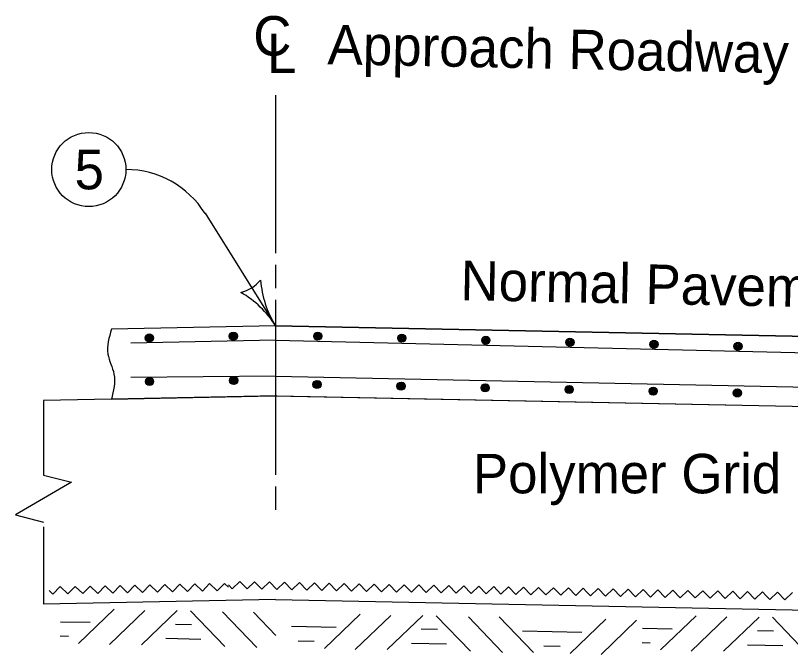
# Model space of a CAD drawing. Extents: x 5546 to 81668, y 3174 to 15999.
# Drawn here: x 17362.5 to 17676.2, y 13836.8 to 14095.5 of the extents above; entities that cross this region are included whole.
import ezdxf

# ---------------------------------------------------------------- set-up
doc = ezdxf.new("R2010")
doc.units = 0
for name, color, linetype in [('PS_BOLT', 7, 'Continuous'), ('PS_CONST', 7, 'Continuous'), ('PS_DIM', 7, 'Continuous'), ('PS_TEXT', 7, 'Continuous')]:
    doc.layers.add(name, color=color, linetype=linetype)

msp = doc.modelspace()

# ---------------------------------------------------------------- linework, layer by layer
at = {"layer": 'PS_BOLT'}
msp.add_line((18199.22, 13934.15), (17467.7, 13949.31), dxfattribs=at)
at = {"layer": 'PS_CONST'}
msp.add_line((17439.18, 14015.41), (17467.75, 13969.86), dxfattribs=at)
for centre, radius, start, end in [((17407.15, 13995.32), 37.81, 32.09, 90), ((17449.85, 13998.4), 15.52, 284.3569, 319.8236), ((17501.78, 13991.2), 40.18, 184.0178, 212.0903), ((17433.71, 13948.52), 40.18, 32.0903, 60.1628)]:
    msp.add_arc(centre, radius, start, end, dxfattribs=at)
at = {"layer": 'PS_DIM'}
for p, q in [((17467.74, 13969.86), (17401.36, 13968.53)), ((17467.74, 13969.86), (17401.36, 13968.53)), ((18178, 13955.6), (17467.74, 13969.86)), ((17467.74, 13969.86), (18178, 13955.6)), ((17467.71, 13964.11), (17409.19, 13962.8)), ((17467.71, 13964.11), (18199.3, 13946.45)), ((17467.71, 13949.54), (17409.18, 13948.92)), ((17468.31, 13941.51), (17401.36, 13940.16)), ((17401.36, 13940.16), (17467.17, 13941.48)), ((17467.17, 13941.51), (17467.74, 13941.5)), ((17467.17, 13941.51), (18216.28, 13926.47)), ((17467.74, 13941.5), (17468.31, 13941.51)), ((17468.31, 13941.48), (18216.28, 13926.47)), ((17401.36, 13940.16), (17373.8, 13939.61)), ((17373.8, 13939.61), (17373.8, 13909.35)), ((17373.8, 13909.35), (17385.15, 13906.52)), ((17385.15, 13906.52), (17373.8, 13899.9)), ((17373.8, 13899.9), (17362.46, 13893.28)), ((17362.46, 13893.28), (17373.8, 13890.44)), ((17373.8, 13888.44), (17373.8, 13857.19)), ((17467.74, 13859.07), (17373.8, 13857.19)), ((17467.74, 13859.07), (18284.33, 13842.68)), ((17402.43, 13855.13), (17388.01, 13841.27)), ((17414.87, 13854.65), (17400.45, 13840.79)), ((17427.88, 13854.61), (17413.46, 13840.76)), ((17433.29, 13854.51), (17447.15, 13840.08)), ((17446.29, 13854.02), (17460.15, 13839.6)), ((17458.75, 13854), (17467.85, 13844.52)), ((17501.96, 13853.13), (17487.54, 13839.27)), ((17514.4, 13852.65), (17499.98, 13838.8)), ((17527.41, 13852.62), (17512.99, 13838.76)), ((17532.82, 13852.51), (17546.68, 13838.09)), ((17545.83, 13852.02), (17559.68, 13837.6)), ((17558.28, 13852), (17572.13, 13837.57)), ((17601.49, 13851.13), (17587.07, 13837.27)), ((17613.94, 13850.65), (17599.51, 13836.8)), ((17638.03, 13852.49), (17623.61, 13838.63)), ((17650.47, 13852.01), (17636.05, 13838.16)), ((17663.48, 13851.98), (17649.06, 13838.12)), ((17668.89, 13851.87), (17682.75, 13837.45))]:
    msp.add_line(p, q, dxfattribs=at)
for points in [[(17467.74, 14063.28), (17467.74, 13999.32)], [(17467.75, 13994.6), (17467.75, 13985.14)], [(17467.74, 13980.41), (17467.74, 13909.51)], [(17418.14, 13964.87), (17417.86, 13965.42), (17417.56, 13966.28), (17416.67, 13966.41), (17415.9, 13966.26), (17415.21, 13965.67), (17415.32, 13964.85), (17415.48, 13963.98), (17416.19, 13963.59), (17416.92, 13963.55), (17417.86, 13964.1), (17417.91, 13964.74), (17417.66, 13965.6), (17417.07, 13966.29), (17416.25, 13966.23), (17415.61, 13965.65), (17415.57, 13964.87), (17415.77, 13964), (17416.27, 13963.89), (17416.86, 13963.74), (17417.56, 13964.18), (17417.52, 13964.81), (17417.37, 13965.53), (17416.94, 13966.04), (17416.23, 13965.74), (17415.83, 13965.18), (17415.84, 13964.44), (17416.24, 13964.28), (17416.69, 13964.07), (17417.25, 13964.45), (17417.36, 13965), (17417.08, 13965.46), (17416.54, 13965.47), (17416.17, 13965.2), (17416.06, 13964.71), (17416.28, 13964.48), (17416.58, 13964.35), (17416.99, 13964.62), (17417.07, 13964.98), (17416.85, 13965.3), (17416.56, 13965.23), (17416.38, 13964.97), (17416.41, 13964.63), (17416.65, 13964.65), (17416.77, 13964.95)], [(17452.17, 13965.63), (17451.9, 13966.18), (17451.59, 13967.04), (17450.7, 13967.16), (17449.94, 13967.01), (17449.24, 13966.43), (17449.35, 13965.6), (17449.51, 13964.74), (17450.22, 13964.35), (17450.95, 13964.3), (17451.89, 13964.86), (17451.94, 13965.5), (17451.69, 13966.36), (17451.1, 13967.05), (17450.28, 13966.99), (17449.64, 13966.41), (17449.6, 13965.62), (17449.8, 13964.76), (17450.3, 13964.65), (17450.89, 13964.5), (17451.59, 13964.94), (17451.55, 13965.57), (17451.4, 13966.29), (17450.98, 13966.79), (17450.26, 13966.5), (17449.86, 13965.94), (17449.87, 13965.2), (17450.27, 13965.04), (17450.72, 13964.82), (17451.28, 13965.21), (17451.39, 13965.75), (17451.11, 13966.22), (17450.57, 13966.23), (17450.2, 13965.96), (17450.09, 13965.46), (17450.31, 13965.23), (17450.61, 13965.11), (17451.03, 13965.38), (17451.1, 13965.73), (17450.88, 13966.06), (17450.59, 13965.99), (17450.42, 13965.73), (17450.44, 13965.39), (17450.68, 13965.41), (17450.81, 13965.71)], [(17483.32, 13965.6), (17483.59, 13966.15), (17483.9, 13967), (17484.79, 13967.13), (17485.56, 13966.98), (17486.24, 13966.39), (17486.14, 13965.57), (17485.97, 13964.7), (17485.26, 13964.32), (17484.53, 13964.27), (17483.59, 13964.83), (17483.54, 13965.46), (17483.8, 13966.33), (17484.39, 13967.01), (17485.21, 13966.95), (17485.85, 13966.37), (17485.89, 13965.59), (17485.68, 13964.73), (17485.19, 13964.61), (17484.59, 13964.46), (17483.89, 13964.9), (17483.94, 13965.54), (17484.09, 13966.25), (17484.52, 13966.76), (17485.23, 13966.47), (17485.62, 13965.9), (17485.62, 13965.17), (17485.22, 13965), (17484.76, 13964.79), (17484.21, 13965.17), (17484.1, 13965.72), (17484.38, 13966.19), (17484.92, 13966.2), (17485.28, 13965.93), (17485.39, 13965.43), (17485.18, 13965.2), (17484.88, 13965.08), (17484.46, 13965.35), (17484.39, 13965.7), (17484.61, 13966.02), (17484.9, 13965.95), (17485.07, 13965.7), (17485.05, 13965.36), (17484.81, 13965.37), (17484.68, 13965.68)], [(17517.35, 13964.78), (17517.62, 13965.33), (17517.93, 13966.18), (17518.82, 13966.31), (17519.59, 13966.16), (17520.28, 13965.57), (17520.17, 13964.75), (17520, 13963.88), (17519.3, 13963.49), (17518.56, 13963.45), (17517.62, 13964.01), (17517.57, 13964.65), (17517.83, 13965.5), (17518.42, 13966.19), (17519.24, 13966.13), (17519.88, 13965.55), (17519.92, 13964.77), (17519.71, 13963.9), (17519.22, 13963.79), (17518.62, 13963.64), (17517.92, 13964.08), (17517.97, 13964.71), (17518.12, 13965.43), (17518.55, 13965.94), (17519.26, 13965.64), (17519.65, 13965.08), (17519.65, 13964.35), (17519.25, 13964.18), (17518.79, 13963.97), (17518.24, 13964.35), (17518.13, 13964.9), (17518.41, 13965.37), (17518.94, 13965.38), (17519.31, 13965.1), (17519.42, 13964.61), (17519.21, 13964.38), (17518.91, 13964.25), (17518.49, 13964.53), (17518.42, 13964.88), (17518.64, 13965.2), (17518.93, 13965.13), (17519.11, 13964.88), (17519.07, 13964.54), (17518.84, 13964.55), (17518.71, 13964.86)], [(17551.38, 13963.96), (17551.65, 13964.5), (17551.96, 13965.36), (17552.85, 13965.49), (17553.62, 13965.33), (17554.3, 13964.75), (17554.19, 13963.92), (17554.03, 13963.06), (17553.32, 13962.67), (17552.59, 13962.63), (17551.65, 13963.19), (17551.6, 13963.82), (17551.86, 13964.69), (17552.44, 13965.37), (17553.27, 13965.31), (17553.91, 13964.73), (17553.95, 13963.94), (17553.74, 13963.08), (17553.25, 13962.97), (17552.65, 13962.82), (17551.95, 13963.26), (17552, 13963.89), (17552.15, 13964.61), (17552.58, 13965.12), (17553.29, 13964.82), (17553.68, 13964.25), (17553.68, 13963.53), (17553.28, 13963.36), (17552.82, 13963.15), (17552.27, 13963.53), (17552.15, 13964.07), (17552.44, 13964.54), (17552.97, 13964.56), (17553.34, 13964.28), (17553.45, 13963.79), (17553.24, 13963.56), (17552.94, 13963.43), (17552.52, 13963.71), (17552.45, 13964.05), (17552.67, 13964.38), (17552.96, 13964.31), (17553.13, 13964.06), (17553.1, 13963.71), (17552.87, 13963.73), (17552.74, 13964.03)], [(17585.41, 13963.13), (17585.68, 13963.68), (17585.99, 13964.54), (17586.88, 13964.67), (17587.65, 13964.51), (17588.33, 13963.93), (17588.22, 13963.1), (17588.06, 13962.24), (17587.35, 13961.85), (17586.62, 13961.81), (17585.68, 13962.36), (17585.63, 13963), (17585.89, 13963.86), (17586.48, 13964.55), (17587.3, 13964.49), (17587.94, 13963.9), (17587.98, 13963.12), (17587.77, 13962.26), (17587.28, 13962.15), (17586.68, 13962), (17585.98, 13962.44), (17586.03, 13963.07), (17586.18, 13963.79), (17586.61, 13964.3), (17587.32, 13964), (17587.71, 13963.44), (17587.71, 13962.7), (17587.31, 13962.54), (17586.85, 13962.33), (17586.3, 13962.71), (17586.19, 13963.26), (17586.47, 13963.72), (17587, 13963.73), (17587.37, 13963.46), (17587.48, 13962.96), (17587.27, 13962.74), (17586.97, 13962.61), (17586.55, 13962.89), (17586.48, 13963.23), (17586.7, 13963.56), (17586.98, 13963.49), (17587.16, 13963.23), (17587.13, 13962.89), (17586.9, 13962.91), (17586.77, 13963.21)], [(17619.43, 13962.31), (17619.71, 13962.86), (17620.02, 13963.72), (17620.91, 13963.84), (17621.68, 13963.69), (17622.36, 13963.11), (17622.26, 13962.28), (17622.09, 13961.42), (17621.38, 13961.03), (17620.65, 13960.99), (17619.71, 13961.54), (17619.66, 13962.18), (17619.92, 13963.04), (17620.51, 13963.73), (17621.33, 13963.67), (17621.97, 13963.08), (17622.01, 13962.3), (17621.8, 13961.44), (17621.31, 13961.33), (17620.71, 13961.18), (17620.01, 13961.62), (17620.06, 13962.25), (17620.21, 13962.97), (17620.63, 13963.48), (17621.35, 13963.18), (17621.74, 13962.61), (17621.74, 13961.88), (17621.33, 13961.72), (17620.88, 13961.51), (17620.33, 13961.89), (17620.21, 13962.43), (17620.5, 13962.9), (17621.03, 13962.91), (17621.4, 13962.64), (17621.51, 13962.14), (17621.3, 13961.91), (17621, 13961.79), (17620.58, 13962.07), (17620.51, 13962.41), (17620.73, 13962.74), (17621.01, 13962.67), (17621.19, 13962.41), (17621.16, 13962.07), (17620.92, 13962.09), (17620.8, 13962.39)], [(17653.47, 13961.49), (17653.74, 13962.04), (17654.05, 13962.9), (17654.94, 13963.03), (17655.71, 13962.87), (17656.39, 13962.28), (17656.29, 13961.46), (17656.12, 13960.6), (17655.41, 13960.21), (17654.68, 13960.17), (17653.74, 13960.72), (17653.69, 13961.36), (17653.95, 13962.22), (17654.54, 13962.91), (17655.36, 13962.85), (17656, 13962.26), (17656.04, 13961.48), (17655.83, 13960.62), (17655.34, 13960.51), (17654.74, 13960.36), (17654.04, 13960.8), (17654.09, 13961.43), (17654.24, 13962.15), (17654.66, 13962.66), (17655.38, 13962.36), (17655.77, 13961.8), (17655.77, 13961.06), (17655.36, 13960.9), (17654.91, 13960.68), (17654.35, 13961.07), (17654.25, 13961.62), (17654.53, 13962.08), (17655.06, 13962.09), (17655.43, 13961.82), (17655.54, 13961.32), (17655.33, 13961.1), (17655.03, 13960.97), (17654.61, 13961.24), (17654.54, 13961.59), (17654.76, 13961.91), (17655.05, 13961.85), (17655.22, 13961.59), (17655.19, 13961.25), (17654.95, 13961.27), (17654.83, 13961.57)], [(17418.26, 13947.26), (17418, 13947.81), (17417.7, 13948.67), (17416.81, 13948.81), (17416.04, 13948.67), (17415.35, 13948.09), (17415.45, 13947.27), (17415.59, 13946.4), (17416.3, 13946), (17417.04, 13945.95), (17417.98, 13946.5), (17418.04, 13947.13), (17417.79, 13948), (17417.21, 13948.69), (17416.39, 13948.64), (17415.74, 13948.07), (17415.69, 13947.28), (17415.89, 13946.42), (17416.38, 13946.3), (17416.98, 13946.14), (17417.68, 13946.57), (17417.64, 13947.21), (17417.5, 13947.93), (17417.08, 13948.44), (17416.37, 13948.15), (17415.96, 13947.59), (17415.96, 13946.86), (17416.36, 13946.69), (17416.81, 13946.48), (17417.37, 13946.85), (17417.48, 13947.39), (17417.22, 13947.86), (17416.68, 13947.88), (17416.3, 13947.61), (17416.18, 13947.12), (17416.39, 13946.89), (17416.69, 13946.76), (17417.11, 13947.03), (17417.19, 13947.38), (17416.98, 13947.7), (17416.69, 13947.63), (17416.51, 13947.38), (17416.53, 13947.04), (17416.77, 13947.06), (17416.9, 13947.36)], [(17452.3, 13947.63), (17452.03, 13948.18), (17451.74, 13949.04), (17450.85, 13949.18), (17450.08, 13949.04), (17449.39, 13948.45), (17449.48, 13947.63), (17449.63, 13946.77), (17450.34, 13946.37), (17451.07, 13946.31), (17452.01, 13946.86), (17452.08, 13947.49), (17451.83, 13948.36), (17451.25, 13949.05), (17450.43, 13949.01), (17449.78, 13948.43), (17449.73, 13947.65), (17449.93, 13946.78), (17450.42, 13946.67), (17451.01, 13946.5), (17451.72, 13946.94), (17451.68, 13947.57), (17451.54, 13948.29), (17451.12, 13948.8), (17450.4, 13948.52), (17450, 13947.96), (17449.99, 13947.23), (17450.4, 13947.05), (17450.84, 13946.84), (17451.41, 13947.21), (17451.52, 13947.76), (17451.25, 13948.23), (17450.71, 13948.25), (17450.34, 13947.98), (17450.22, 13947.48), (17450.43, 13947.25), (17450.73, 13947.12), (17451.15, 13947.39), (17451.23, 13947.74), (17451.02, 13948.07), (17450.73, 13948), (17450.55, 13947.74), (17450.57, 13947.41), (17450.81, 13947.42), (17450.94, 13947.72)], [(17486.03, 13946), (17485.78, 13946.55), (17485.51, 13947.42), (17484.63, 13947.59), (17483.86, 13947.47), (17483.14, 13946.92), (17483.22, 13946.09), (17483.34, 13945.22), (17484.03, 13944.8), (17484.76, 13944.72), (17485.72, 13945.23), (17485.8, 13945.87), (17485.58, 13946.74), (17485.03, 13947.45), (17484.2, 13947.43), (17483.53, 13946.88), (17483.46, 13946.09), (17483.63, 13945.23), (17484.12, 13945.09), (17484.71, 13944.91), (17485.43, 13945.32), (17485.41, 13945.96), (17485.29, 13946.68), (17484.89, 13947.21), (17484.17, 13946.95), (17483.74, 13946.4), (17483.72, 13945.66), (17484.11, 13945.48), (17484.56, 13945.25), (17485.13, 13945.61), (17485.26, 13946.15), (17485, 13946.63), (17484.47, 13946.66), (17484.09, 13946.41), (17483.95, 13945.91), (17484.15, 13945.68), (17484.45, 13945.54), (17484.88, 13945.8), (17484.97, 13946.14), (17484.76, 13946.48), (17484.47, 13946.42), (17484.29, 13946.17), (17484.29, 13945.83), (17484.54, 13945.83), (17484.67, 13946.13)], [(17520.07, 13945.31), (17519.81, 13945.87), (17519.54, 13946.74), (17518.67, 13946.91), (17517.89, 13946.79), (17517.18, 13946.23), (17517.25, 13945.41), (17517.37, 13944.53), (17518.07, 13944.11), (17518.8, 13944.04), (17519.75, 13944.56), (17519.84, 13945.19), (17519.62, 13946.06), (17519.06, 13946.77), (17518.23, 13946.75), (17517.56, 13946.19), (17517.49, 13945.41), (17517.66, 13944.54), (17518.15, 13944.41), (17518.75, 13944.23), (17519.46, 13944.64), (17519.44, 13945.27), (17519.32, 13946), (17518.92, 13946.53), (17518.2, 13946.26), (17517.77, 13945.71), (17517.75, 13944.98), (17518.14, 13944.8), (17518.59, 13944.57), (17519.16, 13944.93), (17519.29, 13945.47), (17519.04, 13945.94), (17518.5, 13945.98), (17518.12, 13945.72), (17517.98, 13945.23), (17518.18, 13945), (17518.48, 13944.85), (17518.91, 13945.12), (17519, 13945.46), (17518.8, 13945.79), (17518.51, 13945.74), (17518.32, 13945.49), (17518.33, 13945.14), (17518.57, 13945.15), (17518.71, 13945.45)], [(17554.1, 13944.63), (17553.85, 13945.19), (17553.58, 13946.06), (17552.69, 13946.22), (17551.93, 13946.1), (17551.21, 13945.55), (17551.28, 13944.72), (17551.4, 13943.85), (17552.1, 13943.44), (17552.83, 13943.36), (17553.79, 13943.87), (17553.87, 13944.5), (17553.65, 13945.38), (17553.09, 13946.09), (17552.27, 13946.06), (17551.6, 13945.51), (17551.53, 13944.73), (17551.69, 13943.86), (17552.19, 13943.73), (17552.78, 13943.55), (17553.49, 13943.96), (17553.47, 13944.59), (17553.36, 13945.32), (17552.95, 13945.84), (17552.23, 13945.58), (17551.81, 13945.03), (17551.78, 13944.3), (17552.17, 13944.11), (17552.62, 13943.88), (17553.2, 13944.24), (17553.32, 13944.78), (17553.07, 13945.26), (17552.53, 13945.29), (17552.15, 13945.04), (17552.02, 13944.55), (17552.22, 13944.31), (17552.52, 13944.17), (17552.94, 13944.43), (17553.03, 13944.77), (17552.83, 13945.11), (17552.54, 13945.05), (17552.35, 13944.8), (17552.36, 13944.46), (17552.61, 13944.47), (17552.74, 13944.76)], [(17588.13, 13943.94), (17587.88, 13944.5), (17587.61, 13945.37), (17586.73, 13945.54), (17585.96, 13945.42), (17585.24, 13944.86), (17585.32, 13944.04), (17585.44, 13943.17), (17586.13, 13942.75), (17586.86, 13942.67), (17587.82, 13943.19), (17587.9, 13943.82), (17587.68, 13944.69), (17587.12, 13945.41), (17586.3, 13945.38), (17585.63, 13944.82), (17585.56, 13944.05), (17585.73, 13943.17), (17586.22, 13943.04), (17586.81, 13942.87), (17587.53, 13943.28), (17587.51, 13943.91), (17587.39, 13944.63), (17586.99, 13945.16), (17586.27, 13944.89), (17585.84, 13944.35), (17585.82, 13943.61), (17586.21, 13943.44), (17586.65, 13943.2), (17587.23, 13943.56), (17587.35, 13944.1), (17587.1, 13944.58), (17586.56, 13944.61), (17586.18, 13944.36), (17586.05, 13943.86), (17586.25, 13943.63), (17586.55, 13943.49), (17586.98, 13943.75), (17587.06, 13944.09), (17586.86, 13944.42), (17586.57, 13944.37), (17586.38, 13944.12), (17586.39, 13943.78), (17586.64, 13943.79), (17586.77, 13944.08)], [(17622.16, 13943.26), (17621.91, 13943.82), (17621.65, 13944.69), (17620.76, 13944.86), (17619.99, 13944.74), (17619.27, 13944.18), (17619.35, 13943.36), (17619.47, 13942.49), (17620.16, 13942.07), (17620.9, 13941.99), (17621.85, 13942.5), (17621.93, 13943.14), (17621.71, 13944.01), (17621.16, 13944.72), (17620.33, 13944.7), (17619.67, 13944.14), (17619.59, 13943.36), (17619.76, 13942.49), (17620.25, 13942.36), (17620.84, 13942.18), (17621.56, 13942.59), (17621.54, 13943.23), (17621.43, 13943.95), (17621.02, 13944.47), (17620.3, 13944.21), (17619.87, 13943.67), (17619.85, 13942.93), (17620.24, 13942.75), (17620.69, 13942.52), (17621.26, 13942.87), (17621.39, 13943.42), (17621.13, 13943.9), (17620.6, 13943.93), (17620.21, 13943.67), (17620.08, 13943.18), (17620.28, 13942.95), (17620.58, 13942.81), (17621.01, 13943.06), (17621.1, 13943.4), (17620.9, 13943.74), (17620.6, 13943.69), (17620.42, 13943.44), (17620.42, 13943.09), (17620.67, 13943.1), (17620.81, 13943.4)], [(17656.2, 13942.58), (17655.95, 13943.14), (17655.68, 13944), (17654.8, 13944.17), (17654.02, 13944.06), (17653.31, 13943.5), (17653.38, 13942.67), (17653.5, 13941.8), (17654.2, 13941.38), (17654.93, 13941.31), (17655.89, 13941.82), (17655.97, 13942.46), (17655.74, 13943.33), (17655.19, 13944.04), (17654.36, 13944.02), (17653.7, 13943.46), (17653.62, 13942.68), (17653.79, 13941.81), (17654.29, 13941.68), (17654.87, 13941.5), (17655.59, 13941.91), (17655.57, 13942.54), (17655.46, 13943.27), (17655.05, 13943.79), (17654.33, 13943.53), (17653.91, 13942.98), (17653.88, 13942.25), (17654.27, 13942.07), (17654.72, 13941.84), (17655.29, 13942.19), (17655.42, 13942.73), (17655.17, 13943.21), (17654.63, 13943.24), (17654.25, 13942.99), (17654.11, 13942.5), (17654.31, 13942.26), (17654.61, 13942.12), (17655.04, 13942.38), (17655.13, 13942.72), (17654.93, 13943.06), (17654.64, 13943), (17654.45, 13942.75), (17654.46, 13942.41), (17654.7, 13942.42), (17654.84, 13942.72)], [(17467.17, 13941.48), (17467.17, 13941.51)], [(17468.31, 13941.51), (17468.31, 13941.48)], [(17467.74, 13904.79), (17467.74, 13895.34)], [(17376.07, 13862.67), (17377.61, 13861.18), (17380.58, 13864.27), (17383.66, 13861.31), (17386.62, 13864.39), (17389.71, 13861.43), (17392.67, 13864.52), (17395.75, 13861.55), (17398.72, 13864.64), (17401.8, 13861.67), (17404.77, 13864.76), (17407.86, 13861.79), (17410.82, 13864.88), (17413.9, 13861.92), (17416.86, 13865), (17419.95, 13862.04), (17422.91, 13865.12), (17426, 13862.16), (17428.97, 13865.24), (17432.05, 13862.28), (17435.01, 13865.36), (17438.1, 13862.4), (17441.06, 13865.49), (17444.15, 13862.52), (17447.11, 13865.61), (17448.66, 13864.12)], [(17448.66, 13864.98), (17450.13, 13863.44), (17453.22, 13866.4), (17456.19, 13863.32), (17459.27, 13866.28), (17462.23, 13863.19), (17465.32, 13866.16), (17468.28, 13863.07), (17471.36, 13866.04), (17474.33, 13862.95), (17477.41, 13865.92), (17480.38, 13862.83), (17483.47, 13865.79), (17486.43, 13862.71), (17489.51, 13865.67), (17492.47, 13862.59), (17495.56, 13865.55), (17498.52, 13862.47), (17501.61, 13865.43), (17504.58, 13862.35), (17507.66, 13865.31), (17510.62, 13862.22), (17513.71, 13865.19), (17516.67, 13862.1), (17519.76, 13865.07), (17521.24, 13863.52)], [(17521.24, 13863.52), (17522.72, 13861.98), (17525.8, 13864.95), (17528.77, 13861.86), (17531.85, 13864.82), (17534.82, 13861.74), (17537.9, 13864.7), (17540.86, 13861.62), (17543.95, 13864.58), (17546.91, 13861.5), (17550, 13864.46), (17552.96, 13861.38), (17556.05, 13864.34), (17559.01, 13861.25), (17562.1, 13864.22), (17565.06, 13861.13), (17568.14, 13864.1), (17571.11, 13861.01), (17574.19, 13863.97), (17577.16, 13860.89), (17580.24, 13863.85), (17583.21, 13860.77), (17586.29, 13863.73), (17589.25, 13860.65), (17592.34, 13863.61), (17593.82, 13862.07)], [(17593.82, 13862.07), (17595.3, 13860.53), (17598.39, 13863.49), (17601.35, 13860.4), (17604.44, 13863.37), (17607.4, 13860.28), (17610.49, 13863.25), (17613.45, 13860.16), (17616.54, 13863.13), (17619.5, 13860.04), (17622.58, 13863), (17625.55, 13859.92), (17628.63, 13862.88), (17631.6, 13859.79), (17634.68, 13862.76), (17637.65, 13859.68), (17640.73, 13862.64), (17643.69, 13859.56), (17646.78, 13862.52), (17649.74, 13859.43), (17652.83, 13862.39), (17655.79, 13859.31), (17658.88, 13862.28), (17661.84, 13859.19), (17664.93, 13862.16), (17666.41, 13860.61)], [(17666.41, 13860.61), (17667.89, 13859.07), (17670.97, 13862.03), (17673.94, 13858.95), (17677.02, 13861.91)], [(17380.71, 13850.09), (17392.74, 13849.84)], [(17427.21, 13849.13), (17433.74, 13849)], [(17474.21, 13848.21), (17492.27, 13847.85)], [(17526.74, 13847.13), (17533.28, 13847)], [(17616.31, 13847.45), (17628.34, 13847.21)], [(17380.59, 13844.29), (17383.86, 13844.22)], [(17567.75, 13846.33), (17591.8, 13845.85)], [(17662.81, 13846.49), (17669.35, 13846.36)], [(17423.26, 13843.35), (17437.45, 13843.07)], [(17476.86, 13842.35), (17483.39, 13842.22)], [(17522.8, 13841.35), (17536.99, 13841.07)], [(17616.2, 13841.65), (17619.46, 13841.58)], [(17658.87, 13840.71), (17673.06, 13840.43)], [(17576.39, 13840.36), (17582.92, 13840.23)]]:
    msp.add_lwpolyline(points, dxfattribs=at)
for centre in [(17416.62, 13964.94), (17450.65, 13965.69), (17484.84, 13965.66), (17518.87, 13964.84), (17552.9, 13964.02), (17586.93, 13963.2), (17620.96, 13962.37), (17654.99, 13961.55), (17416.74, 13947.34), (17450.78, 13947.71), (17484.51, 13946.12), (17518.55, 13945.44), (17552.58, 13944.75), (17586.61, 13944.07), (17620.64, 13943.39), (17654.68, 13942.7)]:
    msp.add_circle(centre, 1.65, dxfattribs=at)
msp.add_spline([(17401.36, 13968.53), (17399.85, 13958.45), (17402.31, 13950.32), (17401.36, 13940.16)], degree=3, dxfattribs=at)
msp.add_spline([(17401.36, 13968.53), (17399.85, 13958.45), (17402.31, 13950.32), (17401.36, 13940.16)], degree=3, dxfattribs=at)
at = {"layer": 'PS_TEXT'}
msp.add_circle((17392.15, 14033.14), 15, dxfattribs=at)

# ---------------------------------------------------------------- texts
at = {"layer": 'PS_CONST'}
for s, p in [('C', (17458.72, 14079.26)), ('L', (17464.26, 14072.19)), ('Polymer Grid', (17547.62, 13902.04))]:
    msp.add_text(s, height=16, dxfattribs=at).set_placement(p)
for s, p in [('Approach Roadway', (17488.7, 14075.8)), ('Normal Pavement Slope', (17542.5, 13980.29))]:
    msp.add_text(s, height=16, rotation=358.8502, dxfattribs=at).set_placement(p)
at = {"layer": 'PS_TEXT'}
msp.add_text('5', height=16, dxfattribs=at).set_placement((17386.38, 14025.13))

doc.saveas('drawing.dxf')
